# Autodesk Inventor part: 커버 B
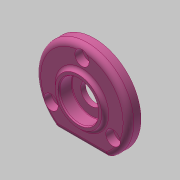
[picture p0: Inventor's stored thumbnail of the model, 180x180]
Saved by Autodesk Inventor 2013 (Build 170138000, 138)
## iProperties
Created: 2020-04
Part Number: 커버 B
Material: 알루미늄 6061
Document SubType Name: Modeling
Designer: mduedu
Density: 1 g/cm^3
Author: mduedu
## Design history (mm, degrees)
sketch "스케치1"
  geometry: C1 r 26 at (0, 0); 1 further point
  constraints: 1 centre point, 1 coincident
  dimensions: "d0" = 52 diameter of C1
extrude "돌출1" new body sketch "스케치1" distance "d1" = 7; taper "d2" = 0 deg
sketch "스케치2"
  geometry: L1 (-14.62, -21.5)-(14.62, -21.5); A1 r 26 centre (0, 0) between (-14.62, -21.5) and (14.62, -21.5) reference; 1 further point
  constraints: 2 end point, 2 point on circle, 1 horizontal
  dimensions: "d3" = 21.5 distance from line of L1 point (0, 0)
extrude "돌출2" cut sketch "스케치2" stored distance "d4" = 7; taper "d5" = 0 deg
sketch "스케치6"
  geometry: C1 r 13 at (0, 0); 1 further point
  constraints: 1 centre point, 1 coincident
  dimensions: "d29" = 26 diameter of C1
extrude "돌출5" join sketch "스케치6" distance "d30" = 2; taper "d31" = 0 deg
fillet "모깎기1" dims "d6" = 3
fillet "모깎기2" dims "d7" = 3
fillet "모깎기4" dims "d33" = 2
sketch "스케치3" dims "d8" = 40
  geometry: 3 further points
  constraints: 2 vertical alignment, 1 coincident, 2 other
hole "구멍1" sketch "스케치3" at (0, 20) diameter "d9" = 4.5; stored, may be unused: countersink angle "d13" = 90 deg, drill point angle "d15" = 118 deg; dims "d10" = 6, "d11" = 8, "d12" = 4.4, "d14" = 8
sketch "스케치4"
  geometry: C1 r 14 at (0, 0); 1 further point
  constraints: 1 centre point, 1 coincident
  dimensions: "d19" = 28 diameter of C1
extrude "돌출3" join sketch "스케치4" distance "d20" = 4; taper "d21" = 0 deg
sketch "스케치5"
  geometry: C1 r 12 at (0, 0); 1 further point
  constraints: 1 centre point, 1 coincident
  dimensions: "d22" = 24 diameter of C1
extrude "돌출4" cut sketch "스케치5" distance "d23" = 3; taper "d24" = 0 deg
fillet "모깎기3" dims "d25" = 3
chamfer "모따기1" distance "d26" = 0.5; stored, may be unused: second distance "d27" = 2, angle "d28" = 45 deg
sketch "스케치7"
  geometry: 2 further points
  constraints: 1 coincident
hole "구멍2" sketch "스케치7" at (0, 0) diameter "d34" = 12; stored, may be unused: countersink angle "d38" = 90 deg, drill point angle "d40" = 118 deg; dims "d35" = 6, "d36" = 22, "d37" = 7.3, "d39" = 8
fillet "모깎기5" dims "d41" = 0.3
chamfer "모따기2" distance "d42" = 0.7; stored, may be unused: second distance "d43" = 2, angle "d44" = 30 deg
node "솔리드1"
pattern_circular "원형 패턴1" dims angle "d17" = 360 deg
node "투영된 루프1"
